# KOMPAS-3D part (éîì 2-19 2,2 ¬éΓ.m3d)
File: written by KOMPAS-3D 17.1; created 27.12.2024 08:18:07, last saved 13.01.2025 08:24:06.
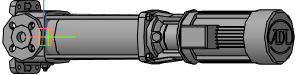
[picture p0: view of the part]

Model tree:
1. Операция без истории:4  (labels: ВМН 2-19 2,2 кВт)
